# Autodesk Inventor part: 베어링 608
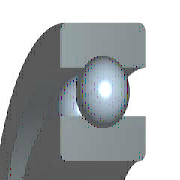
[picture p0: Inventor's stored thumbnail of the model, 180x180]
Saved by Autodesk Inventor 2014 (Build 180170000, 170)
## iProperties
IsCustomPart: 1
Created: 2012-02
Part Number: 베어링 608
Material: 강철, 연강
Description: 깊은 그루브 볼 베어링
Document SubType Name: Modeling
Standard: KS B 2023
Designer: mduedu
Standards Organization: KS
Language: ko-KR
Size Designation: 608 - 8 x 22 x 7
Categories: <MemberInstance><Categories><Category DisplayName="샤프트 부품" InternalName="7f7aeb1f-a693-4053-b835-cee3144e0d98" Mnemonic="SHFT"><Category DisplayName="베어링" Inter
Density: 7.86 g/cm^3
Appearance: 노란색
Mass: 10.9696 g
Surface Area: 20.0754 cm^2
Volume: 1.39562 cm^3
Author: mduedu
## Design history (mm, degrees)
sketch "스케치" dims "d0" = 3.64 (= -0.26 x WD + 0.26 x BD)
  geometry: L1 (1.68, 7.5)-(5.32, 7.5); L2 (3.5, 7.5)-(3.5, 5.68); L3 (3.5, 7.5)-(3.5, 9.32); L4 (2.148, 6.282)-(0, 6.282); L5 (0, 4)-(7, 4); L6 (2.148, 8.718)-(0, 8.718); L7 (0, 11)-(7, 11); L8 (7, 4)-(7, 6.282); L9 (4.852, 6.282)-(7, 6.282); L10 (4.852, 8.718)-(7, 8.718); L11 (7, 11)-(7, 8.718); L12 (-1.4, 0)-(8.4, 0) reference; L13 (0, -0.3)-(0, 5.3) reference
  constraints: 22 end point, 4 point on line, 2 collinear, 2 perpendicular, 2 symmetric about line, 1 midpoint, 1 parallel, 14 other
  dimensions: "d9" = 8 diameter of L5 L12 (= WD); "d11" = 22 diameter of L7 L12 (= BD); "d12" = 7 distance between parallel lines of L8 L13 (= KB); "d13" = 12.564 diameter of L9 L12 (= 0.326 x BD + 0.674 x WD)
revolve "본체" stored, may be unused: angle "d6" = 90 deg
revolve "볼" stored, may be unused: angle "d7" = 90 deg
pattern_circular "IDS_ARRAYBALL[SIMPL:T]" dims angle "d3" = 360 deg
body "Solid1"
fillet "모깎기1" dims "d1" = 0.3 (= KRS)
other parameters: "WD" = 8 [user parameter; used in 5 equation terms], "BD" = 22 [user parameter; used in 5 equation terms], "KB" = 7 [user parameter; used in 1 equation term], "KRS" = 0.3 [user parameter; used in 1 equation term], "d4" = 0, "d5" = 0, "d8" = 0, "d14" = 0, "d15" = 0, "BBA" = 0 [user parameter], "BC0" = 1370000 [user parameter], "BC" = 3250000 [user parameter], "BR" = 11 (= 0.5 x BD) [user parameter], "WR" = 4 (= 0.5 x WD) [user parameter]
